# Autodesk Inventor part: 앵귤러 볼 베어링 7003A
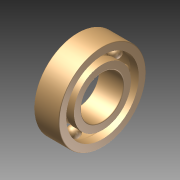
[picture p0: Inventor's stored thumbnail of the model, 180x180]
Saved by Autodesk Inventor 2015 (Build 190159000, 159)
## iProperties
Created: 2024-12
Part Number: 앵귤러 볼 베어링 7003A
Material: 일반
Document SubType Name: Modeling
Designer: 10401
Density: 1 g/cm^3
Appearance: 기본값
Author: 10401
Author: jhkim
Description: 앵귤러 콘택트 볼 베어링
Creation Date: 2024-11-28
Sending System: Autodesk Inventor 2025
Preprocessor: ST-DEVELOPER v20
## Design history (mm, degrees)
node "앵귤러 볼 베어링 7003A1"
body "Solid1"
node "Solid1_1"
node "Solid1_2"
node "Solid1_3"
node "Solid1_4"
node "Solid1_5"
node "Solid1_6"
node "Solid1_7"
node "Solid1_8"
node "Solid1_9"
node "Solid1_10"
node "기준1"
node "기준2"
node "기준3"
node "기준4"
node "기준5"
node "기준6"
node "기준7"
node "기준8"
node "기준9"
node "기준10"
node "기준11"
